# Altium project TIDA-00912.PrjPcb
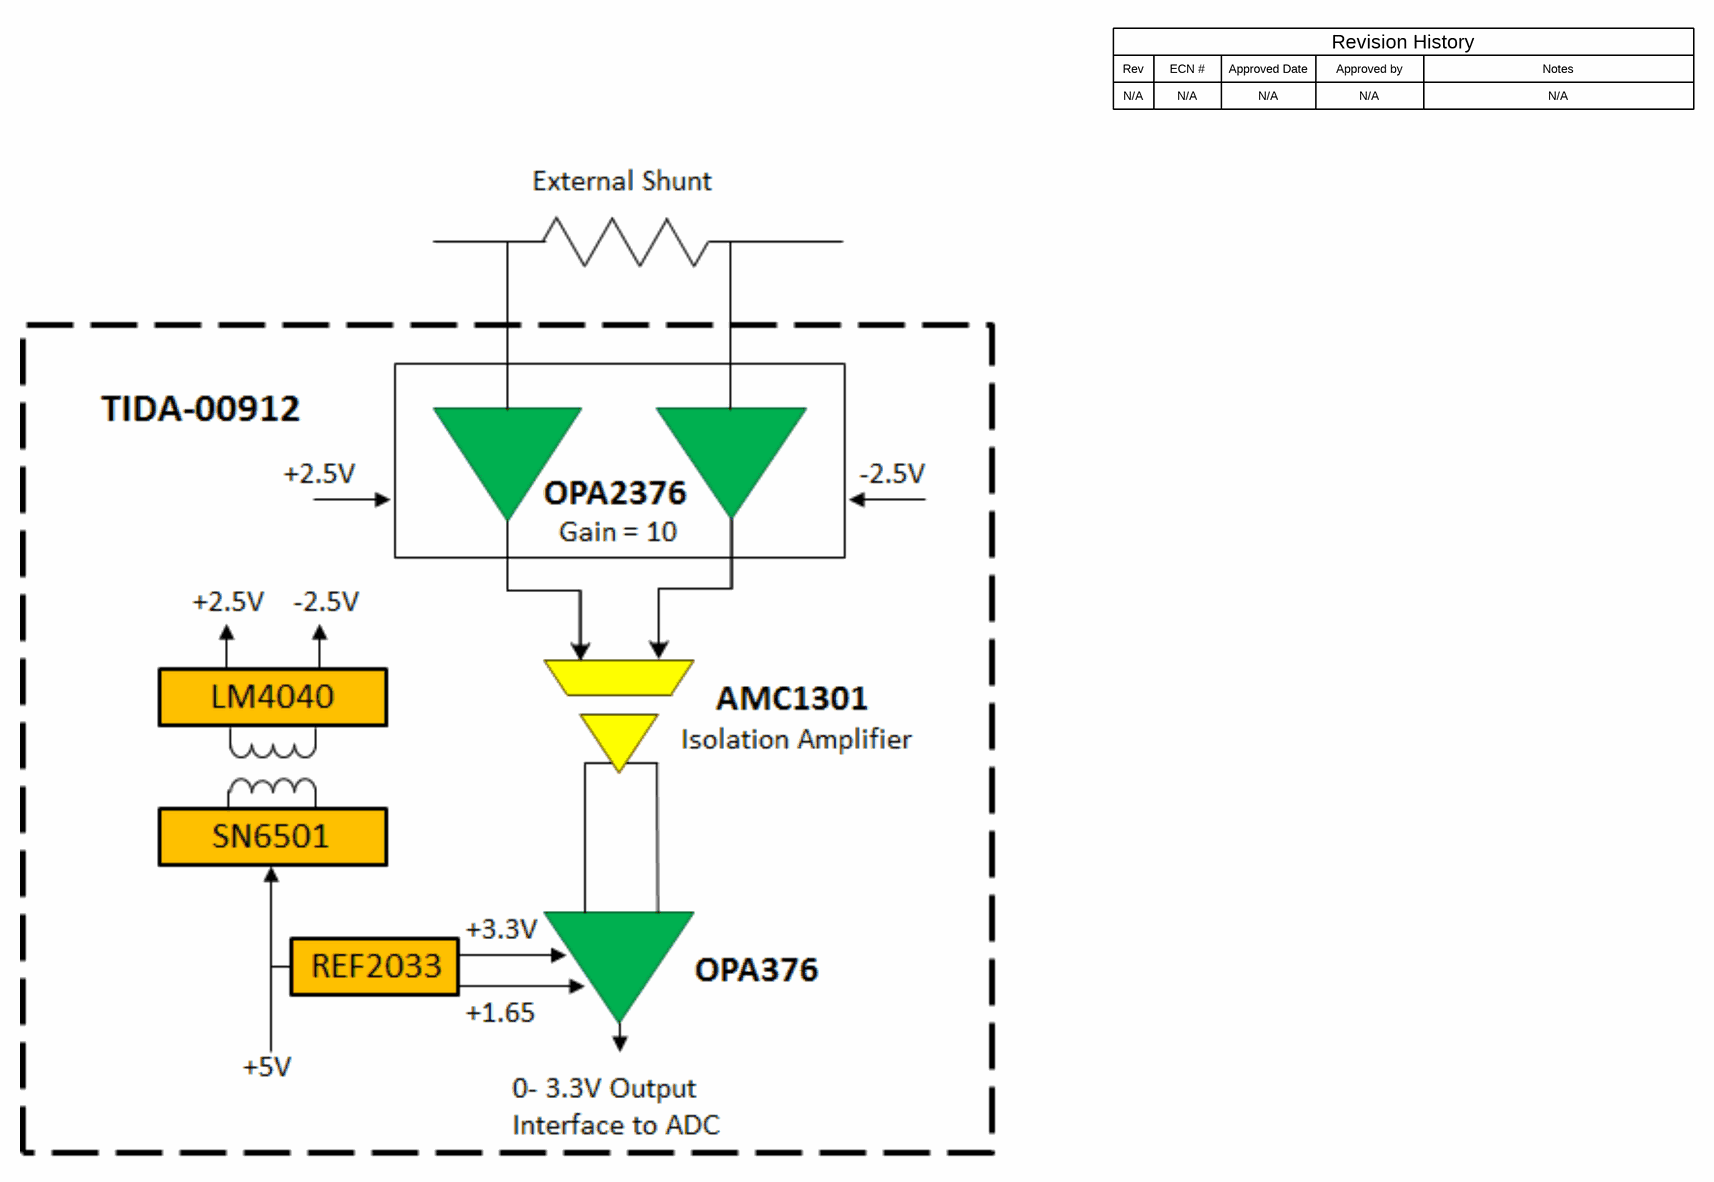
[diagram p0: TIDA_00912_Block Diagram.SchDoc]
TID: TIDA-00912; TechSupport: http://www.ti.com/support; SCH_Rev: E1; PRJ_Title: Shunt Design; PRJ_Number: TIDA-00912; PRJ_Engineer: Neha Nain; PRJ_Customer: Public Release; PCB_Rev: E1; PCB_Layout: Avinash N; EVM_Orderable: N/A; CopyrightYear: 2016
3 sheets, 80 parts. Net scope: flat (ports and power ports of the same name join across sheets).
Board file: TIDA-00912.PcbDoc
Sheets:
  TIDA_00912_Block Diagram.SchDoc
  TIDA_00912_Schematic.SchDoc
  TIDA_00912_TID_Hardware.SchDoc

## Sheet TIDA_00912_Block Diagram.SchDoc: Block diagram
size 431 x 279 mm; Date: Not shown in title block; ApprovedBy: Not shown in title block; CheckedBy: Not shown in title block; Author: Not shown in title block; CompanyName: Not shown in title block; DrawnBy: Neha Nain; Engineer: Not shown in title block; Organization: Not shown in title block; Address1: Not shown in title block; Address2: Not shown in title block; Address3: Not shown in title block; Address4: Not shown in title block; DocumentNumber: 1; Revision: Use project parameter SCH_Rev; SheetNumber: 1; SheetTotal: 3; PageSetup: Record=PageOptions¦CenterHorizontal=True¦CenterVertical=True¦PrintScale=1.00¦XCorrection=1.00¦YCorrection=1.00¦PrintKind=0¦BorderSize=5000000¦LeftOffset=0¦BottomOffset=0¦Orientation=2¦PaperLength=1000¦PaperWidth=1000¦Scale=100¦PaperSource=15¦PrintQuality=600¦MediaType=1¦DitherType=10¦PaperKind=Letter¦PrintScaleMode=1

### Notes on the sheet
- Rev
- N/A
- ECN #
- Approved Date
- Approved by
- Revision History
- Notes

## Sheet TIDA_00912_Schematic.SchDoc: isolated current sense circuit
size 431 x 279 mm; Date: Not shown in title block; ApprovedBy: Not shown in title block; CheckedBy: Not shown in title block; Author: Not shown in title block; CompanyName: Not shown in title block; DrawnBy: Neha Nain; Engineer: Not shown in title block; Organization: Not shown in title block; Address1: Not shown in title block; Address2: Not shown in title block; Address3: Not shown in title block; Address4: Not shown in title block; DocumentNumber: 1; Revision: Use project parameter SCH_Rev; SheetNumber: 2; SheetTotal: 3; PageSetup: Record=PageOptions¦CenterHorizontal=True¦CenterVertical=True¦PrintScale=1.00¦XCorrection=1.00¦YCorrection=1.00¦PrintKind=0¦BorderSize=5000000¦LeftOffset=0¦BottomOffset=0¦Orientation=2¦PaperLength=1000¦PaperWidth=1000¦Scale=100¦PaperSource=15¦PrintQuality=600¦MediaType=1¦DitherType=10¦PaperKind=Letter¦PrintScaleMode=1
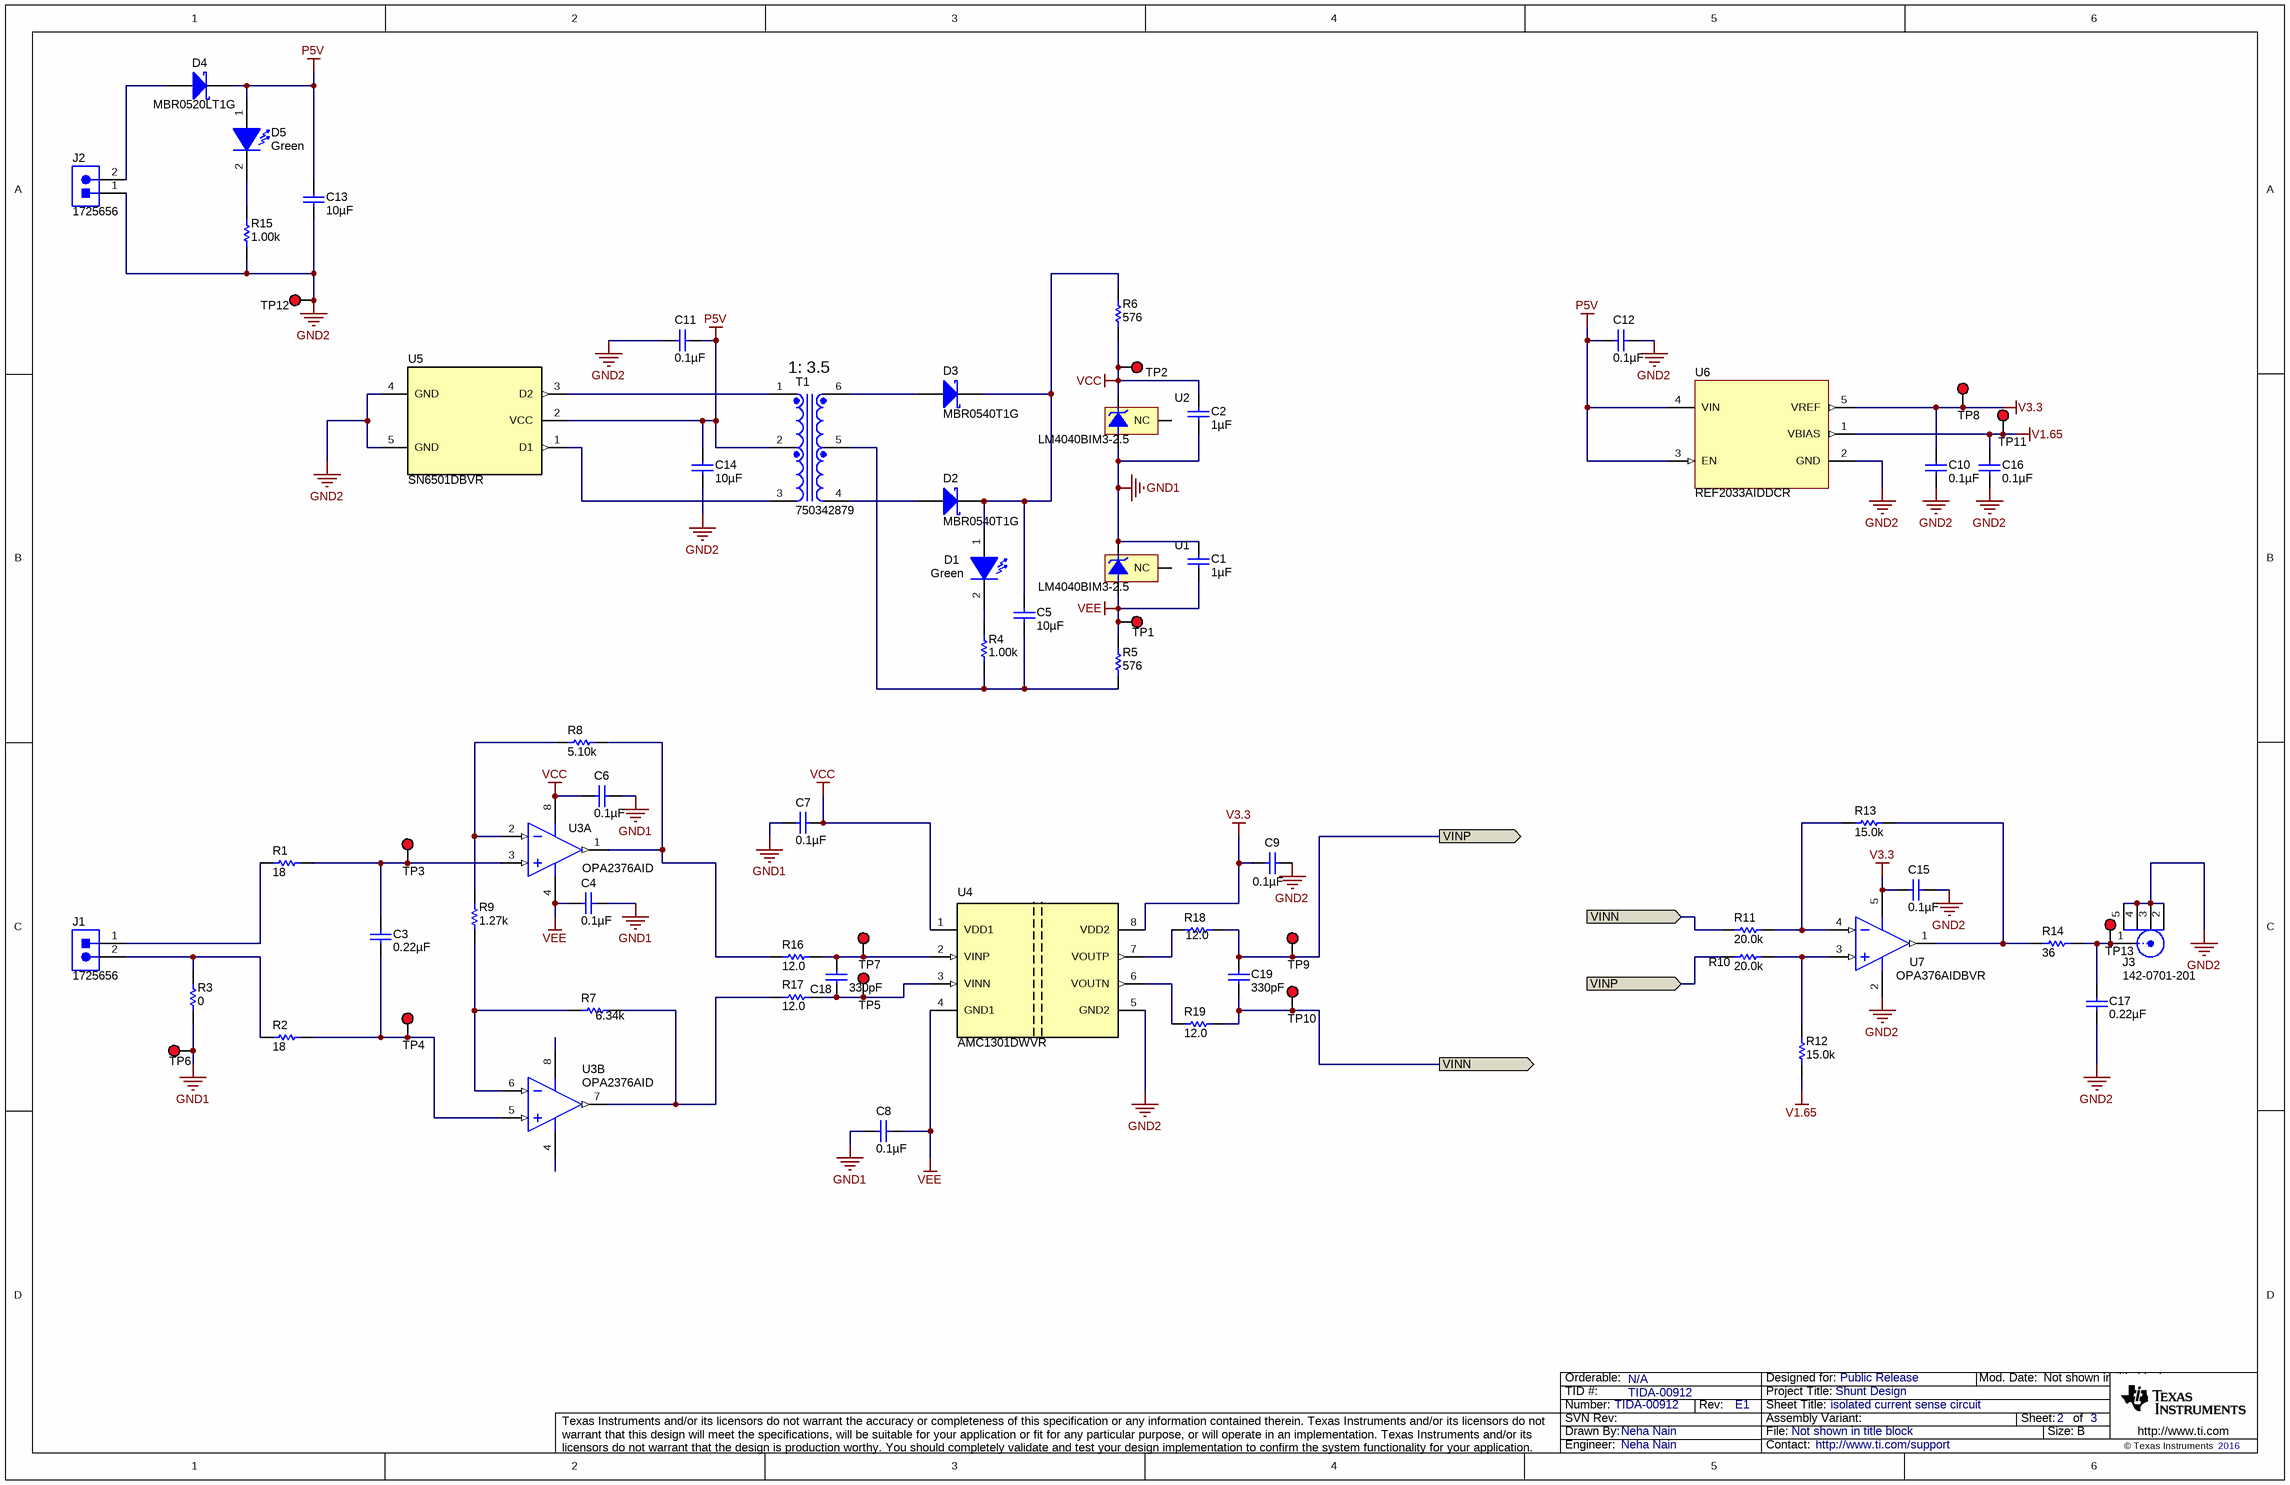
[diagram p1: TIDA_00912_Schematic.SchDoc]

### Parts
C1  ValueDisplayed: 1µF  [0603]  (hidden comment: C1608X7R1E105K080AB)
C2  ValueDisplayed: 1µF  [0603]  (hidden comment: C1608X7R1E105K080AB)
C3  ValueDisplayed: 0.22µF  [0603]  (hidden comment: GRM188R71E224KA88D)
C4  ValueDisplayed: 0.1µF  [0603]  (hidden comment: C0603C104J3RAC)
C5  ValueDisplayed: 10µF  [0603]  (hidden comment: GRM188R6YA106MA73)
C6  ValueDisplayed: 0.1µF  [0603]  (hidden comment: C0603C104J3RAC)
C7  ValueDisplayed: 0.1µF  [0603]  (hidden comment: C0603C104J3RAC)
C8  ValueDisplayed: 0.1µF  [0603]  (hidden comment: C0603C104J3RAC)
C9  ValueDisplayed: 0.1µF  [0603]  (hidden comment: C0603C104J3RAC)
C10  ValueDisplayed: 0.1µF  [0603]  (hidden comment: C0603C104J3RAC)
C11  ValueDisplayed: 0.1µF  [0603]  (hidden comment: C0603C104J3RAC)
C12  ValueDisplayed: 0.1µF  [0603]  (hidden comment: C0603C104J3RAC)
C13  ValueDisplayed: 10µF  [0603]  (hidden comment: C1608X5R1E106M080AC)
C14  ValueDisplayed: 10µF  [0805_HV]  (hidden comment: C2012X5R1E106K125AB)
C15  ValueDisplayed: 0.1µF  [0603]  (hidden comment: C0603C104J3RAC)
C16  ValueDisplayed: 0.1µF  [0603]  (hidden comment: C0603C104J3RAC)
C17  ValueDisplayed: 0.22µF  [0603]  (hidden comment: C0603C224J3RAC7867)
C18  ValueDisplayed: 330pF  [0603]  (hidden comment: C1608C0G1H331J)
C19  ValueDisplayed: 330pF  [0603]  (hidden comment: C1608C0G1H331J)
D1  value Green  [LG L29K_GREEN]  (hidden comment: LG L29K-G2J1-24-Z)
D2  MBR0540T1G  [SOD-123]
D3  MBR0540T1G  [SOD-123]
D4  MBR0520LT1G  [SOD-123]
D5  value Green  [LG L29K_GREEN]  (hidden comment: LG L29K-G2J1-24-Z)
J1  1725656  [CONN_1725656]
J2  1725656  [CONN_1725656]
J3  142-0701-201  [Johnson_142-0701-20x]
R1  ValueDisplayed: 18  [0603]  (hidden comment: CRCW060318R0JNEA)
R2  ValueDisplayed: 18  [0603]  (hidden comment: CRCW060318R0JNEA)
R3  ValueDisplayed: 0  [0402]  (hidden comment: CRCW04020000Z0ED)
R4  ValueDisplayed: 1.00k  [0603]  (hidden comment: ERJ-3EKF1001V)
R5  ValueDisplayed: 576  [0603]  (hidden comment: CRCW0603576RFKEA)
R6  ValueDisplayed: 576  [0603]  (hidden comment: CRCW0603576RFKEA)
R7  ValueDisplayed: 6.34k  [0603]  (hidden comment: CRCW06036K34FKEA)
R8  ValueDisplayed: 5.10k  [0603]  (hidden comment: RG1608P-512-B-T5)
R9  ValueDisplayed: 1.27k  [0603]  (hidden comment: RT0603BRD071K27L)
R10  ValueDisplayed: 20.0k  [0603]  (hidden comment: CRCW060320K0FKEA)
R11  ValueDisplayed: 20.0k  [0603]  (hidden comment: CRCW060320K0FKEA)
R12  ValueDisplayed: 15.0k  [0603]  (hidden comment: RC0603FR-0715KL)
R13  ValueDisplayed: 15.0k  [0603]  (hidden comment: RC0603FR-0715KL)
R14  ValueDisplayed: 36  [0603]  (hidden comment: CRCW060336R0JNEA)
R15  ValueDisplayed: 1.00k  [0603]  (hidden comment: ERJ-3EKF1001V)
R16  ValueDisplayed: 12.0  [0603]  (hidden comment: RT0603BRD0712RL)
R17  ValueDisplayed: 12.0  [0603]  (hidden comment: RT0603BRD0712RL)
R18  ValueDisplayed: 12.0  [0603]  (hidden comment: RT0603BRD0712RL)
R19  ValueDisplayed: 12.0  [0603]  (hidden comment: RT0603BRD0712RL)
T1  750342879  [Wurth_750342879]
TP1  5000  [Keystone5000]  (value not drawn)
TP2  5000  [Keystone5000]  (value not drawn)
TP3  5000  [Keystone5000]  (value not drawn)
TP4  5000  [Keystone5000]  (value not drawn)
TP5  5000  [Keystone5000]  (value not drawn)
TP6  5000  [Keystone5000]  (value not drawn)
TP7  5000  [Keystone5000]  (value not drawn)
TP8  5000  [Keystone5000]  (value not drawn)
TP9  5000  [Keystone5000]  (value not drawn)
TP10  5000  [Keystone5000]  (value not drawn)
TP11  5000  [Keystone5000]  (value not drawn)
TP12  5000  [Keystone5000]  (value not drawn)
TP13  5000  [Keystone5000]  (value not drawn)
U1  LM4040BIM3-2.5  [MF03A_N]
U2  LM4040BIM3-2.5  [MF03A_N]
U3  OPA2376AID  [D0008A_N]  (parts A,B of 2)
U4  AMC1301DWVR  [DWV0008A]
U5  SN6501DBVR  [DBV0005A_N]
U6  REF2033AIDDCR  [DDC0005A_N]
U7  OPA376AIDBVR  [DBV0005A_N]

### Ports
VINN (in), VINN (out), VINP (in), VINP (out)

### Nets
GND1: C1.1 C2.2 C4.1 C6.2 C7.2 C8.2 R3.1 TP6.1 U1.1(+V) U2.2(-V)
GND2: C9.1 C10.2 C11.2 C12.1 C13.2 C14.2 C15.1 C16.2 C17.2 J2.1 J3.2 J3.3 J3.4 J3.5 R15.1 TP12.1 U4.5(GND2) U5.4(GND) U5.5(GND) U6.2(GND) U7.2(V-)
P5V: C11.1 C12.2 C13.1 C14.1 D4.1(K) D5.1(A) T1.2 U5.2(VCC) U6.3(EN) U6.4(VIN)
V1.65: C16.1 R12.1 TP11.1 U6.1(VBIAS)
V3.3: C9.2 C10.1 C15.2 TP8.1 U4.8(VDD2) U6.5(VREF) U7.5(V+)
VCC: C2.1 C6.1 C7.1 R6.1 TP2.1 U2.1(+V) U3.8(V+) U4.1(VDD1)
VEE: C1.2 C4.2 C8.1 R5.2 TP1.1 U1.2(-V) U3.4(V-) U4.4(GND1)
VINN: C19.2 R11.1 R19.2 TP10.1 ; port VINN
VINP: C19.1 R10.1 R18.2 TP9.1 ; port VINP
NetC3_1: C3.1 R1.2 TP3.1 U3.3(IN_A+)
NetC3_2: C3.2 R2.2 TP4.1 U3.5(IN_B+)
NetC5_1: C5.1 D1.1(A) D2.1(K) D3.1(K) R6.2
NetC5_2: C5.2 R4.1 R5.1 T1.5
NetC17_1: C17.1 J3.1 R14.2 TP13.1
NetC18_1: C18.1 R16.2 TP7.1 U4.2(VINP)
NetC18_2: C18.2 R17.2 TP5.1 U4.3(VINN)
NetD1_2: D1.2(K) R4.2
NetD2_2: D2.2(A) T1.4
NetD3_2: D3.2(A) T1.6
NetD4_2: D4.2(A) J2.2
NetD5_2: D5.2(K) R15.2
NetJ1_1: J1.1 R1.1
NetJ1_2: J1.2 R2.1 R3.2
NetR7_1: R7.1 R9.1 U3.6(IN_B-)
NetR7_2: R7.2 R17.1 U3.7(OUT_B)
NetR8_1: R8.1 R9.2 U3.2(IN_A-)
NetR8_2: R8.2 R16.1 U3.1(OUT_A)
NetR10_2: R10.2 R12.2 U7.3(IN+)
NetR11_2: R11.2 R13.1 U7.4(IN-)
NetR13_2: R13.2 R14.1 U7.1(OUT)
NetR18_1: R18.1 U4.7(VOUTP)
NetR19_1: R19.1 U4.6(VOUTN)
NetT1_1: T1.1 U5.3(D2)
NetT1_3: T1.3 U5.1(D1)

Not connected (* = marked no-connect by the designer): U1 3(NC); U2 3(NC)

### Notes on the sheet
- (near T1) 1: 3.5

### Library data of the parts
C1 C2 = C1608X7R1E105K080AB: CAP, CERM, 1 µF, 25 V, +/- 10%, X7R, 0603; Manufacturer: TDK; Polarized: N; CompType: Capacitor; Value: 1uF; U/M: EA; Cap_F: 0.000001; Tolerance_%: 10; Value1: Unknown; VDC_V: 25; Value2: 25V; TaMin_C: -55; TaMax_C: 125; AEC Category: Q200
C3 = GRM188R71E224KA88D: CAP, CERM, 0.22 µF, 25 V, +/- 10%, X7R, 0603; Manufacturer: MuRata; Polarized: N; CompType: Capacitor; Value: 0.22uF; U/M: EA; Cap_F: 0.00000022; Tolerance_%: 10; Value1: Unknown; VDC_V: 25; Value2: 25V; TaMin_C: -55; TaMax_C: 125; AEC Category: Q200
C4 C6-C12 C15 C16 = C0603C104J3RAC: CAP, CERM, 0.1 µF, 25 V, +/- 5%, X7R, 0603; Manufacturer: Kemet; Polarized: N; CompType: Capacitor; Value: 0.1uF; U/M: EA; Cap_F: 0.0000001; Tolerance_%: 5; Value1: Unknown; VDC_V: 25; Value2: 25V; TaMin_C: -55; TaMax_C: 125
C5 = GRM188R6YA106MA73: CAP, CERM, 10 µF, 35 V, +/- 20%, X5R, 0603; Manufacturer: Nichicon; Polarized: N; CompType: Capacitor; Value: 10uF; U/M: EA; Cap_F: 0.00001; Tolerance_%: 20; Value1: Unknown; VDC_V: 35; Value2: 35V; TaMin_C: -55; TaMax_C: 85; AEC Category: Q200
C13 = C1608X5R1E106M080AC: CAP, CERM, 10 µF, 25 V, +/- 20%, X5R, 0603; Manufacturer: TDK; Polarized: N; CompType: Capacitor; Value: 10uF; U/M: EA; Cap_F: 0.00001; Tolerance_%: 20; Value1: Unknown; VDC_V: 25; Value2: 25V; TaMin_C: -55; TaMax_C: 85; AEC Category: Q200
C14 = C2012X5R1E106K125AB: CAP, CERM, 10 µF, 25 V, +/- 10%, X5R, 0805; Manufacturer: TDK; Polarized: N; CompType: Capacitor; Value: 10uF; U/M: EA; Cap_F: 0.00001; Tolerance_%: 10; Value1: Unknown; VDC_V: 25; Value2: 25V; TaMin_C: -55; TaMax_C: 85; Cap_Case: 0805; AEC Category: Q200
C17 = C0603C224J3RAC7867: CAP, CERM, 0.22 µF, 25 V, +/- 5%, X7R, 0603; Manufacturer: Kemet; Polarized: N; CompType: Capacitor; Value: 0.22uF; U/M: EA; Cap_F: 0.00000022; Tolerance_%: 5; Value1: Unknown; VDC_V: 25; Value2: 25V; TaMin_C: -55; TaMax_C: 125; AEC Category: Q200
C18 C19 = C1608C0G1H331J: CAP, CERM, 330 pF, 50 V, +/- 5%, C0G/NP0, 0603; Manufacturer: TDK; Polarized: N; CompType: Capacitor; Value: 330pF; U/M: EA; Cap_F: 0.00000000033; Tolerance_%: 5; ESR_ohm: 0.1096; Value1: 0.1096 ohm; VDC_V: 50; Value2: 50V; TaMin_C: -55; TaMax_C: 125; AEC Category: Q200
D1 D5 = LG L29K-G2J1-24-Z: LED, Green, SMD; Manufacturer: OSRAM; Vf_V: 1.7; Value2: 1.7V; Io_A: 0.002; Tjmax_C: 110; Value1: W; U/M: EA
D2 D3 = MBR0540T1G: Diode, Schottky, 40 V, 0.5 A, SOD-123; Manufacturer: ON Semiconductor; U/M: EA; Vf_V: 0.51; Value: 40V; Value1: 0.5A; Value2: 0.51V; Io_A: 0.5; Vr_V: 40; TJmax_C: 150; RJC_CperW: 118; AEC Category: Q101
D4 = MBR0520LT1G: Diode, Schottky, 20 V, 0.5 A, SOD-123; Manufacturer: ON Semiconductor; U/M: EA; Vf_V: 0.385; Value: 20V; Value1: 0.5A; Value2: 0.385V; Io_A: 0.5; Vr_V: 20; TJmax_C: 125; RJC_CperW: 150
J1 J2 = 1725656: Terminal Block, 100mil, 2x1, 6A, 63V, TH; Manufacturer: Phoenix Contact; SymbolCreator: a0412235; U/M: EA
J3 = 142-0701-201: Connector, TH, SMA; Manufacturer: Emerson Network Power; SymbolCreator: X0208326; U/M: EA
R1 R2 = CRCW060318R0JNEA: RES, 18, 5%, 0.1 W, 0603; Manufacturer: Vishay-Dale; CompType: Resistor; Value: 18; Value_Code: 18R0; Tolerance_%: 5; Power_W: 0.1; Value2: 0.1W; VDC_V: 75; TempCo: 200 ppm/C; EIA_Code: E24; U/M: EA; AEC Category: Q200
R3 = CRCW04020000Z0ED: RES, 0, 5%, 0.063 W, 0402; Manufacturer: Vishay-Dale; CompType: Resistor; Value: 0; Value_Code: 0000; Tolerance_%: 5; Power_W: 0.063; Value2: 0.063W; VDC_V: 50; TempCo: 200 ppm/C; EIA_Code: E24; U/M: EA
R4 R15 = ERJ-3EKF1001V: RES, 1.00 k, 1%, 0.1 W, 0603; Manufacturer: Panasonic; CompType: Resistor; Value: 1.00k; Res_ohm: 1000; Value_Code: 1k00; Tolerance_%: 1; Power_W: 0.1; Value2: 0.1W; VDC_V: 75; TempCo: 100 ppm/C; EIA_Code: E96; U/M: EA; AEC Category: Q200
R5 R6 = CRCW0603576RFKEA: RES, 576, 1%, 0.1 W, 0603; Manufacturer: Vishay-Dale; CompType: Resistor; Value: 576; Value_Code: 576R; Tolerance_%: 1; Power_W: 0.1; Value2: 0.1W; VDC_V: 75; TempCo: 100 ppm/C; EIA_Code: E96; U/M: EA; AEC Category: Q200
R7 = CRCW06036K34FKEA: RES, 6.34 k, 1%, 0.1 W, 0603; Manufacturer: Vishay-Dale; CompType: Resistor; Value: 6.34k; Res_ohm: 6340; Value_Code: 6k34; Tolerance_%: 1; Power_W: 0.1; Value2: 0.1W; VDC_V: 75; TempCo: 100 ppm/C; EIA_Code: E96; U/M: EA
R8 = RG1608P-512-B-T5: RES, 5.10 k, 0.1%, 0.1 W, 0603; Manufacturer: Susumu Co Ltd; CompType: Resistor; Value: 5.10k; Res_ohm: 5100; Value_Code: 5k10; Tolerance_%: 0.1; Value2: 0.1W; VDC_V: 75; TempCo: 25 ppm/C; U/M: EA
R9 = RT0603BRD071K27L: RES, 1.27 k, 0.1%, 0.1 W, 0603; Manufacturer: Yageo America; CompType: Resistor; Value: 1.27k; Res_ohm: 1270; Value_Code: 1k27; Tolerance_%: 0.1; Value2: 0.1W; VDC_V: 75; TempCo: 25 ppm/C; EIA_Code: E192; U/M: EA
R10 R11 = CRCW060320K0FKEA: RES, 20.0 k, 1%, 0.1 W, 0603; Manufacturer: Vishay-Dale; CompType: Resistor; Value: 20.0k; Res_ohm: 20000; Value_Code: 20k0; Tolerance_%: 1; Power_W: 0.1; Value2: 0.1W; VDC_V: 75; TempCo: 100 ppm/C; EIA_Code: E96; U/M: EA; AEC Category: Q200
R12 R13 = RC0603FR-0715KL: RES, 15.0 k, 1%, 0.1 W, 0603; Manufacturer: Yageo America; CompType: Resistor; Value: 15.0k; Res_ohm: 15000; Value_Code: 15k0; Tolerance_%: 1; Power_W: 0.1; Value2: 0.1W; VDC_V: 150; TempCo: 200 ppm/C; SizeArea_mm2: 1.28; SizeX_mm: 1.6; SizeY_mm: 0.8; EIA_Code: E96; U/M: EA; AEC Category: Q200
R14 = CRCW060336R0JNEA: RES, 36, 5%, 0.1 W, 0603; Manufacturer: Vishay-Dale; CompType: Resistor; Value: 36; Value_Code: 36R0; Tolerance_%: 5; Power_W: 0.1; Value2: 0.1W; VDC_V: 75; TempCo: 200 ppm/C; EIA_Code: E24; U/M: EA; AEC Category: Q200
R16-R19 = RT0603BRD0712RL: RES, 12.0, 0.1%, 0.1 W, 0603; Manufacturer: Yageo America; CompType: Resistor; Value: 12.0; Res_ohm: 12; Value_Code: 12R0; Tolerance_%: 0.1; Value2: 0.1W; VDC_V: 75; TempCo: 25 ppm/C; EIA_Code: E192; U/M: EA; AEC Category: Q200
T1 = 750342879: Transformer, 50 uH, SMT; Manufacturer: Wurth Elektronik; SymbolCreator: Altium; Value: 50 uH; U/M: EA
TP1-TP13 = 5000: Test Point, Miniature, Red, TH; Manufacturer: Keystone; CompType: Test Point Loop; U/M: EA
U1 U2 = LM4040BIM3-2.5: Precision Micropower Shunt Voltage Reference, 3-pin SOT-23; Manufacturer: Texas Instruments; PackageTopMarking: R2B*XTT; PowerWise: N; CompType: Voltage Reference IC
U3 = OPA2376AID: Precision, Low Noise, Low Quiescent Current Operational Amplifier, 2 to 5.5 V, -40 to 125 degC, 8-pin SOIC (D0008A), Green (RoHS & no Sb/Br); Manufacturer: Texas Instruments; Alternate PartNumber: Equivalent; CMRR(Min)(dB): 76; IIB(Max)(pA): 10; Iq per channel(Max)(mA): 0.95; Number of Channels: 2; Offset Drift(Typ)(uV/C): 0.32; Sub Family: Low Input Bias Current Amp (<=10pA), Low Noise Amp (<=10nV/rtHz), Low Offset Voltage Amplifier (<=500uV), Low Supply Voltage Amplifier (<=2.7V), Precision Amplifier; Total Supply Voltage(Max)(+5V is 5, +/-5V is 10): 5.5; Vio (25C)(Max)(mV): 0.025; Vn at 1kHz(Typ)(nV/rtHz): 7.5
U4 = AMC1301DWVR: 200 kHz, Fully-Differential Isolation Amplifier, DWV0008A; Manufacturer: Texas Instruments; SymbolCreator: Altium; SizeArea_mm2: 67.275; SizeX_mm: 11.5; SizeY_mm: 5.85; SizeZ_mm: 2.8; CompType: IC; U/M: EA
U5 = SN6501DBVR: Transformer Driver for Isolated Power Supplies, DBV0005A; Alternate PartNumber: SN6501DBVT; Manufacturer: Texas Instruments; SymbolCreator: a0411947; CompType: IC; U/M: EA
U6 = REF2033AIDDCR: Low-Drift, Low-Power, Dual-Output, VREF and VREF / 2 Voltage References, DDC0005A; Alternate PartNumber: REF2033AIDDCT; Manufacturer: Texas Instruments; SymbolCreator: a0799628; CompType: IC; U/M: EA
U7 = OPA376AIDBVR: Precision, Low Noise, Low Iq Operational Amplifier, 2.2 to 5.5 V, -40 to 125 degC, 5-pin SOT23 (DBV0005A), Green (RoHS & no Sb/Br); Manufacturer: Texas Instruments; Alternate PartNumber: Equivalent; CMRR(Min)(dB): 76; IIB(Max)(pA): 10; Iq per channel(Max)(mA): 0.95; Number of Channels: 1; Offset Drift(Typ)(uV/C): 0.32; Slew Rate(Typ)(V/us): 2; Sub Family: Low Input Bias Current Amp (<=10pA), Low Noise Amp (<=10nV/rtHz), Low Offset Voltage Amplifier (<=500uV), Low Supply Voltage Amplifier (<=2.7V), Precision Amplifier; Total Supply Voltage(Max)(+5V is 5, +/-5V is 10): 5.5; Total Supply Voltage(Min)(+5V is 5, +/-5V is 10): 2.2; Vio (25C)(Max)(mV): 0.025; Vn at 1kHz(Typ)(nV/rtHz): 7.5

## Sheet TIDA_00912_TID_Hardware.SchDoc: Hardware components
size 431 x 279 mm; Date: Not shown in title block; ApprovedBy: Not shown in title block; CheckedBy: Not shown in title block; Author: Not shown in title block; CompanyName: Not shown in title block; DrawnBy: Neha Nain; Engineer: Not shown in title block; Organization: Not shown in title block; Address1: Not shown in title block; Address2: Not shown in title block; Address3: Not shown in title block; Address4: Not shown in title block; DocumentNumber: 1; Revision: Use project parameter SCH_Rev; SheetNumber: 3; SheetTotal: 3; PageSetup: Record=PageOptions¦CenterHorizontal=True¦CenterVertical=True¦PrintScale=1.00¦XCorrection=1.00¦YCorrection=1.00¦PrintKind=0¦BorderSize=5000000¦LeftOffset=0¦BottomOffset=0¦Orientation=2¦PaperLength=1000¦PaperWidth=1000¦Scale=100¦PaperSource=15¦PrintQuality=600¦MediaType=1¦DitherType=10¦PaperKind=Letter¦PrintScaleMode=1
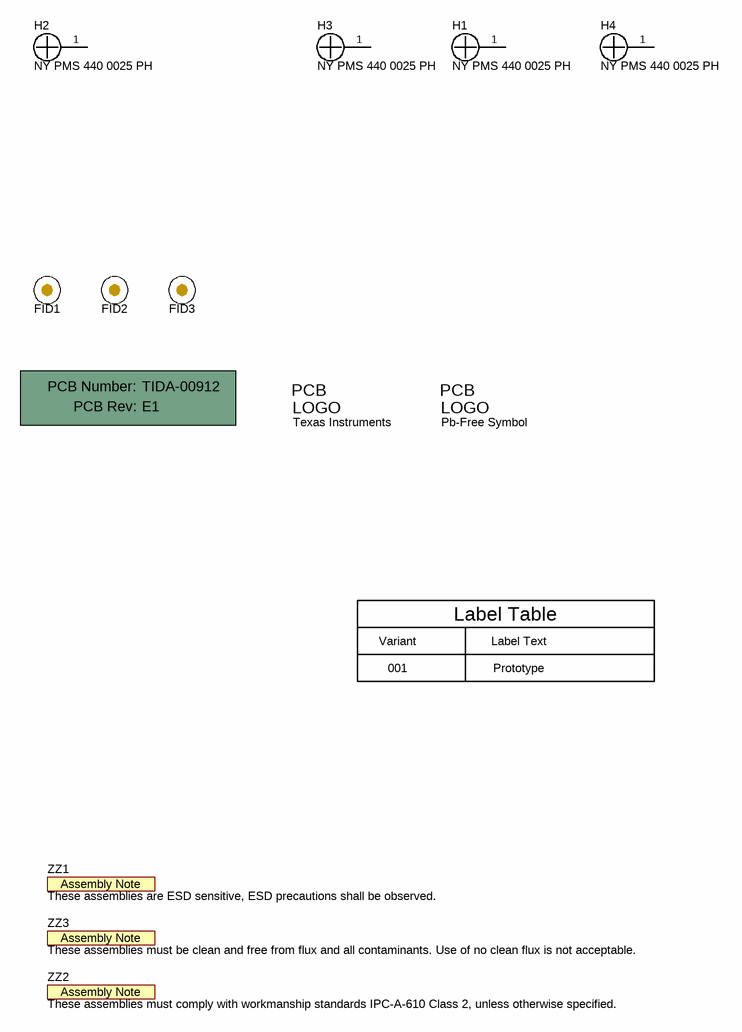
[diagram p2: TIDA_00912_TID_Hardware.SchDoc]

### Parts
!PCB  Printed Circuit Board  (value not drawn)  (mechanical)
FID1  Fiducial  [Fiducial10-20]  (value not drawn)
FID2  Fiducial  [Fiducial10-20]  (value not drawn)
FID3  Fiducial  [Fiducial10-20]  (value not drawn)
H1  NY PMS 440 0025 PH  [NY PMS 440 0025 PH]
H2  NY PMS 440 0025 PH  [NY PMS 440 0025 PH]
H3  NY PMS 440 0025 PH  [NY PMS 440 0025 PH]
H4  NY PMS 440 0025 PH  [NY PMS 440 0025 PH]
Logo1  Texas Instruments  [TI_Stacked_Overlay_Small]  (no BOM)
Logo2  Pb-Free Symbol  [Pb-Free_Overlay_Small]  (no BOM)
ZZ1  These assemblies are ESD sensitive, ESD precautions shall be observed.  [AssemblyNote]  (no BOM)
ZZ2  These assemblies must comply with workmanship standards IPC-A-610 Class 2, unless otherwise specified.  [AssemblyNote]  (no BOM)
ZZ3  These assemblies must be clean and free from flux and all contaminants. Use of no clean flux is not acceptable.  [AssemblyNote]  (no BOM)

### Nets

Not connected (* = marked no-connect by the designer): H1 1; H2 1; H3 1; H4 1

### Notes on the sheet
- Variant
- Label Table
- Label Text
- 001
- Prototype

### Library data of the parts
!PCB = PCB: Manufacturer: Any; PartNumber: TIDA-00912; SymbolCreator: a0412235
FID1-FID3 = Fiducial: Fiducial mark.  There is nothing to buy or mount.; SymbolCreator: codlsc
H1-H4 = NY PMS 440 0025 PH: Machine Screw, Round, #4-40 x 1/4, Nylon, Philips panhead; Manufacturer: B&F Fastener Supply; CompType: Hardware; SymbolCreator: codlsc; U/M: EA
Logo1 = TI_Logo: Texas Instrument Corporate Signature; SymbolCreator: codlsc
Logo2 = Pb-Free: SymbolCreator: a0412235
ZZ1-ZZ3 = AssemblyNote: SymbolCreator: codlsc

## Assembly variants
001: not fitted FID1 FID2 FID3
